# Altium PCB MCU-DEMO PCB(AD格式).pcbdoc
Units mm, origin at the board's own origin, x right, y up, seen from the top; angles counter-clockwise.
Board outline 119.08 x 143.32 mm, 2 copper layers (Top Layer, Bottom Layer); 31 components, 42 nets, 139 pads, 76 vias.
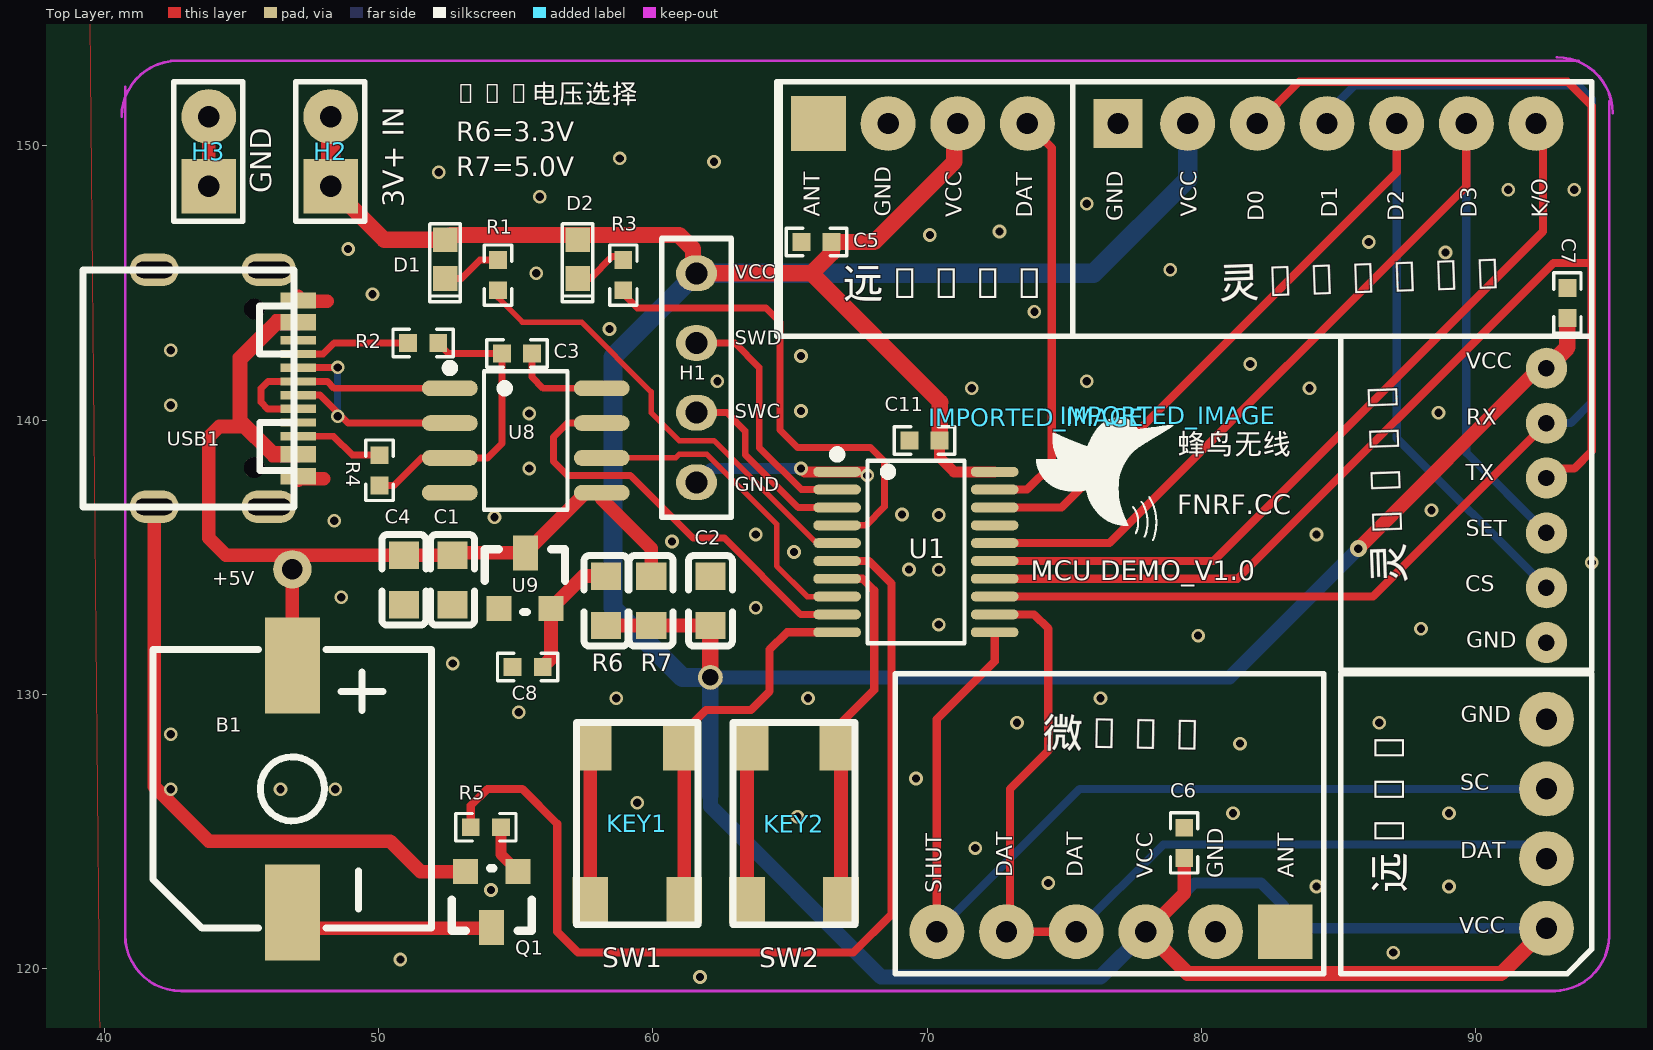
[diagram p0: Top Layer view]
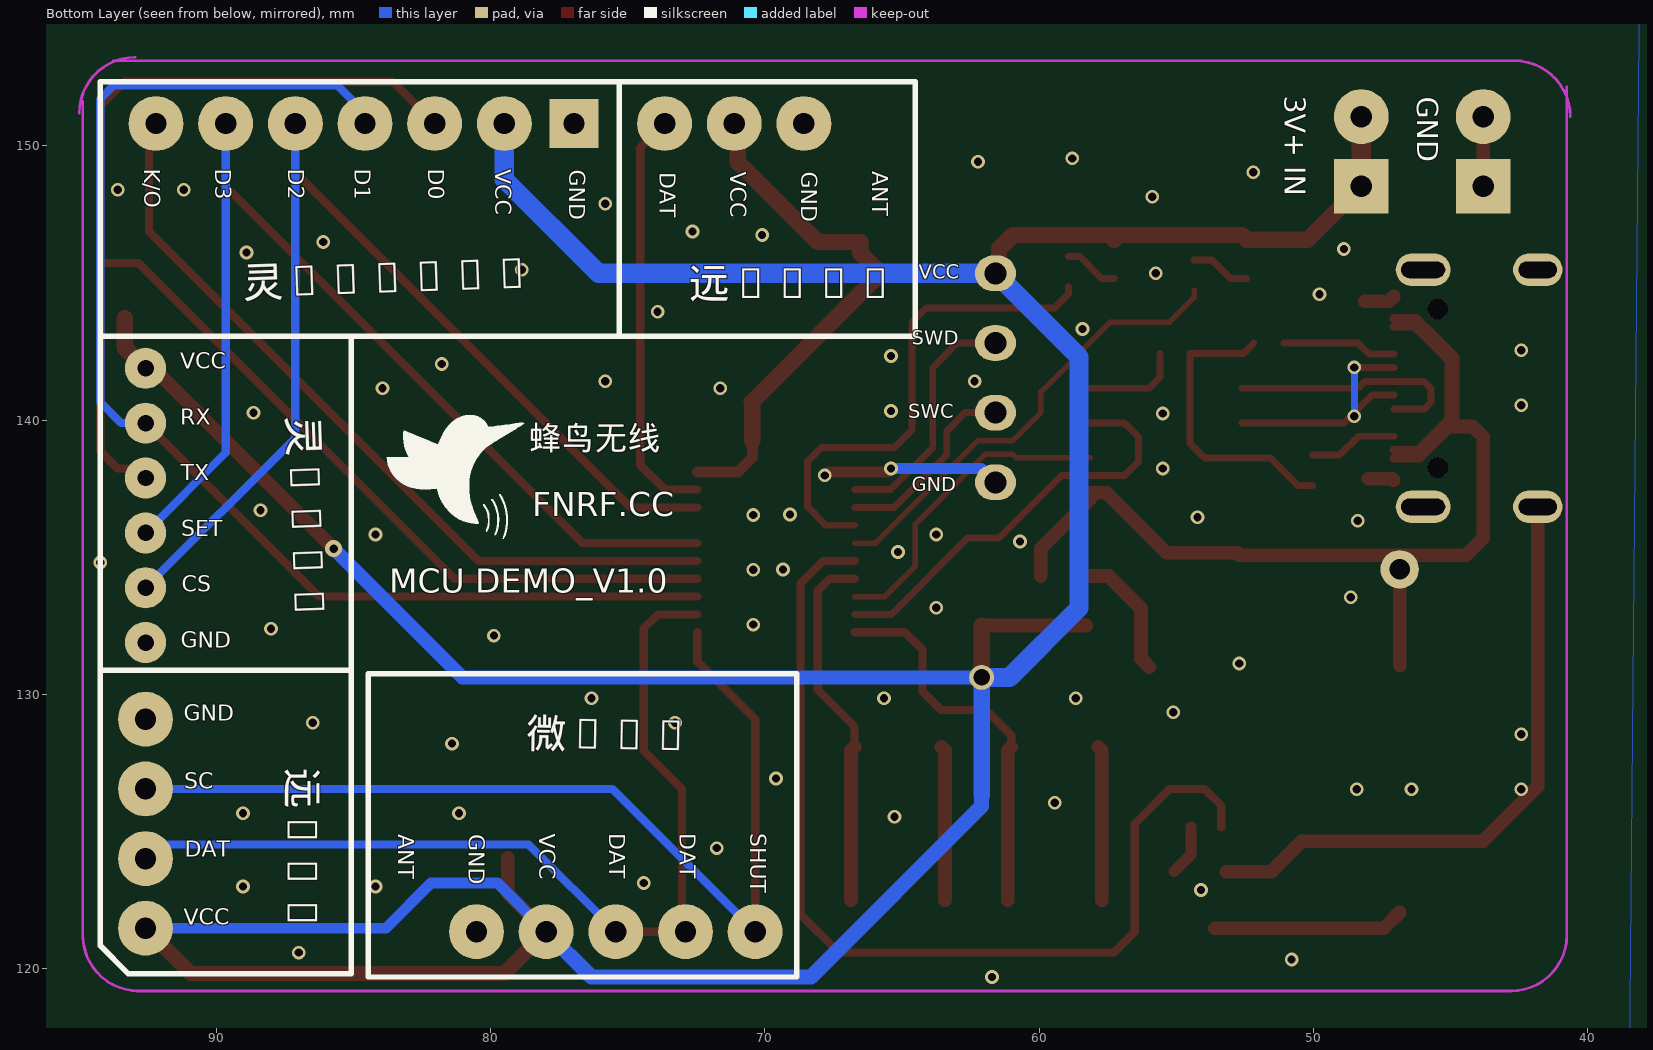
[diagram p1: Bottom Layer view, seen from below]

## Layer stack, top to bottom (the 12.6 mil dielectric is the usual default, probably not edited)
Top Layer: signal copper (thickness not stored)
Dielectric: dielectric 0.32, FR-4, Dk 4.8
Bottom Layer: signal copper (thickness not stored)

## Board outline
144.479,25.4 25.4,25.4 25.4,168.725 144.479,168.725

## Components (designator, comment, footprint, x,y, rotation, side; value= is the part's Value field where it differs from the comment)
B1 "有源蜂鸣器" BUZ-SMD_L9.6-W9.6-LS10.0-R 46.863,126.561 r90 top
C1 "10UF" C0603 52.705,134.181 r270 top
C2 "10UF" C0603 62.103,133.419 r270 top
C3 "0.1u-NC" R0603/0402 55.753,142.436 r180 top
C4 "0.1u-NC" C0603 50.927,134.181 r90 top
C5 "104" R0603/0402 66.675,146.5 r180 top
C6 "104" R0603/0402 79.375,123.894 r90 top
C7 "104" R0603/0402 93.345,144.976 r270 top
C8 "104" R0603/0402 54.737,131.006 r0 top
C11 "104" R0603/0402 70.612,139.261 r180 top
D1 "翠绿LED" LED0603 52.451,145.865 r270 top
D2 "翠绿LED" LED0603 57.277,145.865 r270 top
H1 "HDR-F-2.54_1x4" HDR-F-2.54_1X4 61.595,141.547 r90 top
H2 "3V+ IN" HDR-F-2.54_1X2 48.26,149.802 r90 top
H3 "GND" HDR-F-2.54_1X2 43.815,149.802 r90 top
IMPORTED_IMAGE "IMPORTED_IMAGE" IMPORTED_IMAGE 78.785,140.181 r0 top
IMPORTED_IMAGE "IMPORTED_IMAGE" IMPORTED_IMAGE 73.979,140.103 r0 top
KEY1 "SW1" KEY-SMD-4X4 59.436,125.291 r270 top
KEY2 "SW2" KEY-SMD-4X4 65.151,125.291 r270 top
Q1 "9014" SOT23 54.229,122.624 r90 top
R1 "1k" R0603/0402 54.356,145.992 r270 top
R2 "5.1k" R0603/0402 50.927,142.817 r0 top
R3 "1k" R0603/0402 58.928,145.992 r270 top
R4 "5.1k" R0603/0402 50.038,138.88 r270 top
R5 "1k" R0603/0402 53.213,125.164 r0 top
R6 "10UF" C0603 58.293,133.419 r270 top
R7 "10UF" C0603 59.944,133.419 r270 top
U1 "PY32F002AF15P6TU" TSSOP-20_L6.5-W4.4-P0.65-LS6.4-BL 69.596,135.197 r270 top
U8 "CH340N-NC" SOP-8_L5.0-W4.0-P1.27-LS6.0-BL 55.372,139.261 r270 top
U9 "XC6206P332" SOT23 55.245,134.054 r270 top
USB1 "USB3-TypeC-16p-2" USB-TYPE-C_16PIN-MALE-TYPE-C-31-M-12 44.45,141.166 r270 top

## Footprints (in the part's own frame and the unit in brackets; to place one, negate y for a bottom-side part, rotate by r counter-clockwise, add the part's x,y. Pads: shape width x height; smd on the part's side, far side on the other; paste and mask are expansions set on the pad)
BUZ-SMD_L9.6-W9.6-LS10.0-R [mm]
  rect 3.5x2 smd paste+0 mask+0.051: 1(4.5,0) 2(-4.5,0)
  silkscreen extent -5.08,-5.08 5.08,5.08
C0603 [mm]
  rect 1x1.1 smd paste+0 mask+0.102: 1(-0.9,0) 2(0.9,0)
  silkscreen extent -1.65,-0.8 1.65,0.8
HDR-F-2.54_1X2 [mm]
  rect 2x2 hole 0.78 paste+0 mask+0.102: 1(-1.27,0)
  round 2 hole 0.78 paste+0 mask+0.102: 2(1.27,0)
  silkscreen extent -2.54,-1.24 2.54,1.27
HDR-F-2.54_1X4 [mm]
  oval 1.3x1.5 hole 0.8 paste+0 mask+0.051: 1(-3.81,0) 2(-1.27,0) 3(1.27,0) 4(3.81,0)
  silkscreen extent -5.08,-1.27 5.08,1.27
IMPORTED_IMAGE [mm]
KEY-SMD-4X4 [mm]
  rect 1.7x1.3 smd paste+0 mask+0.102: 1(-2.794,1.587) 2(-2.794,-1.588) 3(2.794,1.715) 4(2.794,-1.714)
  silkscreen extent -3.68,-2.22 3.68,2.22
LED0603 [mm]
  rect 0.9x0.9 smd paste+0 mask+0.051: 1(-0.714,-0.012) 2(0.696,-0.012)
  silkscreen extent -1.3,-0.58 1.55,0.54
R0603/0402 [mm]
  rect 0.65x0.65 smd paste+0 mask+0.051: 1(0.152,0) 2(1.252,0)
  silkscreen extent -0.4,-0.5 1.8,0.5
SOP-8_L5.0-W4.0-P1.27-LS6.0-BL [mm]
  oval 0.574x2.036 smd paste+0 mask+0.051: 1(-1.905,-2.768) 2(-0.635,-2.768) 3(0.635,-2.768) 4(1.905,-2.768) 5(1.905,2.768) 6(0.635,2.768) 7(-0.635,2.768) 8(-1.905,2.768)
  silkscreen extent -2.79,-2.92 2.53,1.52
SOT23 [mil]
  rect 36x36 smd paste+0 mask+2: 1(36.19,41.31) 2(36.19,-33.68)
  rect 50x36 smd paste+0 mask+2: 3(-43.81,4.31)
  silkscreen extent -49,-54 41,61
TSSOP-20_L6.5-W4.4-P0.65-LS6.4-BL [mm]
  oval 0.364x1.742 smd paste+0 mask+0.051: 1(-2.925,-2.871) 2(-2.275,-2.871) 3(-1.625,-2.871) 4(-0.975,-2.871) 5(-0.325,-2.871) 6(0.325,-2.871) 7(0.975,-2.871) 8(1.625,-2.871) 9(2.275,-2.871) 10(2.925,-2.871) 11(2.925,2.871) 12(2.275,2.871) 13(1.625,2.871) 14(0.975,2.871) 15(0.325,2.871) 16(-0.325,2.871) 17(-0.975,2.871) 18(-1.625,2.871) 19(-2.275,2.871) 20(-2.925,2.871)
  silkscreen extent -3.71,-3.02 3.33,1.77
USB-TYPE-C_16PIN-MALE-TYPE-C-31-M-12 [mm]
  oval 1.2x2 hole 0.6 slot 1.6 at 90 deg paste+0 mask+0.051: 0(-4.32,1.556) 0(4.32,1.556)
  oval 1.2x1.8 hole 0.6 slot 1.4 at 90 deg paste+0 mask+0.051: 0(-4.32,-2.624) 0(4.32,-2.624)
  rect 0.3x1.3 smd paste+0 mask+0.051: A1(-3.35,2.623) A4(-2.55,2.623) A5(-1.25,2.623) A6(-0.25,2.623) A7(0.25,2.623) A8(1.25,2.624) A9(2.55,2.623) A12(3.35,2.623) B1(3.05,2.623) B4(2.25,2.623) B5(1.75,2.623) B6(0.75,2.623) B7(-0.75,2.623) B8(-1.75,2.624) B9(-2.25,2.623) B12(-3.05,2.623)
  round 0.75 hole 0.75 slot 0.755 at 0 deg unplated paste+0 mask+0.051: ""(-2.89,1.026) ""(2.89,1.026)
  silkscreen extent -4.32,-5.23 4.32,2.47

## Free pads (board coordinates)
  rect 2x2 smd paste+0 mask+0.102: 1(66.04,150.818) 1(83.058,121.354)
  rect 1.8x1.8 hole 0.78 paste+0 mask+0.102: 1(76.962,150.818)
  round 1.5 hole 0.6 paste+0 mask+0.102: 1(92.583,141.895) 2(92.583,139.895) 3(92.583,137.895) 4(92.583,135.895) 5(92.583,133.895) 6(92.583,131.895)
  round 2 hole 0.78 paste+0 mask+0.102: 2(68.58,150.818) 2(79.502,150.818) 2(80.518,121.354) 3(71.12,150.818) 3(77.978,121.354) 3(82.042,150.818) 3(92.583,121.481) 4(73.66,150.818) 4(75.438,121.354) 4(84.582,150.818) 4(92.583,124.021) 5(72.898,121.354) 5(87.122,150.818) 5(92.583,126.561) 6(70.358,121.354) 6(89.662,150.818) 6(92.583,129.101) 7(92.202,150.818)
  round 0.9 hole 0.6 paste+0 mask+0.102: 3(62.103,130.625)
  round 1.4 hole 0.75 paste+0 mask+0.102: 21(46.863,134.566)

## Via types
v1: diameter 0.5, hole 0.3, Top Layer to Bottom Layer, tented both sides, 75 vias
v2: diameter 0.62, hole 0.31, Top Layer to Bottom Layer, tented both sides, 1 vias

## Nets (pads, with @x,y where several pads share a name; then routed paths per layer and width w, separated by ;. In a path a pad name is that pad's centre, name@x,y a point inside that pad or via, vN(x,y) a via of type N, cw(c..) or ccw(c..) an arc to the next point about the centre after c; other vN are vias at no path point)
+5V: B1.1 C1.1 C4.2 pad.21 R7.1 U8.5 U9.3 USB1.A4 USB1.A9 USB1.B4 USB1.B9 | length 45.6
  Top Layer w0.3: 45.671,142.995 45.593,143.071 46.238,143.716 USB1.A4 ; 45.847,143.325 44.831,142.314 44.831,139.896 46.111,138.616 USB1.A9 ; USB1.B4 46.192,138.916 45.085,140.023 45.085,142.182 46.319,143.416 USB1.B9
  Top Layer w0.5: 45.012,139.769 44.196,139.769 43.815,139.388 43.815,135.705 44.439,135.081 48.529,135.081 ; B1.1 pad.21 46.863,135.08 50.927,135.08 C1.1 ; C1.1 52.791,135.167 U9.3 57.544,137.356 U8.5 58.14,137.128 59.944,135.324 R7.1
D1_2: D1.2 R1.1 | length 2.2
  Top Layer w0.25: D1.2 53.025,145.169 53.695,145.84 R1.1
D+: U8.1 USB1.A6 USB1.B6 | length 9.1
  Top Layer w0.25: USB1.B6 45.962,140.416 45.72,140.658 45.72,141.166 45.97,141.416 USB1.A6 ; USB1.A6@47.074,141.415 48.138,141.415 48.387,141.166 U8.1
D-: U8.2 USB1.A7 USB1.B7 | length 9.2
  Top Layer w0.25: USB1.A7 47.875,140.916 48.895,139.896 U8.2 ; USB1.B7 47.085,141.928 v1(48.514,141.928)
  Bottom Layer w0.25: v1(48.514,140.15) v1(48.514,141.928)
GND: C1.2 C2.1 C3.2 C4.1 C5.2 C6.2 C7.1 C8.1 C11.2 H1.1 H3.1 H3.2 KEY1.2 KEY1.4 KEY2.2 KEY2.4 pad.1@76.962,150.818 pad.2@68.58,150.818 pad.2@80.518,121.354 pad.6@92.583,129.101 pad.6@92.583,131.895 Q1.1 R2.2 R4.2 U1.1 U8.3 U9.2 USB1.0 USB1.A1 USB1.A12 USB1.B1 USB1.B12 | length 56.1
  Top Layer w0.25: R4.2 50.563,137.628 51.562,138.626 U8.3 53.975,138.626 54.5,139.152 C3.2 52.56,142.436 R2.2
  Top Layer w0.4: v1(65.405,138.245) 65.528,138.122 U1.1 67.687,138.122 v1(67.818,137.991)
  Top Layer w0.5: USB1.0@41.825,136.846 41.825,126.645 43.815,124.656 50.419,124.656 51.532,123.543 Q1.1 ; H3.1 H3.2 ; USB1.A12 47.121,137.864 48.006,137.864 ; USB1.A1 47.248,144.341 48.133,144.341 ; KEY1.4 57.721,127.958 KEY1.2 ; KEY2.4 63.436,127.958 KEY2.2
  Bottom Layer w0.4: H1.1 62.103,138.245 v1(65.405,138.245)
  other v1: 61.722,119.703 50.8,120.338 86.995,120.592 54.102,122.878 84.201,123.005 89.027,123.005 74.422,123.132 71.755,124.402 65.278,125.545 81.153,125.672 89.027,125.672 59.436,126.053 42.429,126.55 46.429,126.55 48.429,126.55 69.596,126.942 81.407,128.212 42.429,128.55 73.279,128.974 86.487,128.974 55.118,129.355 58.674,129.863 65.659,129.863 76.327,129.863 52.705,131.133 79.883,132.149 88.011,132.403 70.429,132.55 63.754,133.165 48.641,133.546 70.429,134.55 69.342,134.562 94.234,134.816 65.151,135.197 60.706,135.578 63.754,135.832 84.201,135.832 48.387,136.34 54.229,136.467 69.088,136.562 70.429,136.55 88.392,136.721 55.499,138.245 55.499,140.245 88.646,140.277 65.405,140.341 42.429,140.55 71.628,141.166 83.947,141.166 62.357,141.42 75.819,141.42 81.788,142.055 65.405,142.341 42.429,142.55 58.42,143.325 73.914,143.96 49.784,144.595 55.753,145.357 78.867,145.484 88.9,146.119 48.895,146.246 86.106,146.5 70.104,146.754 72.644,146.881 75.819,147.897 55.88,148.151 91.186,148.405 93.599,148.405 52.197,149.04 62.23,149.421 58.801,149.548
KEY_LED: pad.7 U1.15 | length 29
  Top Layer w0.3: U1.15 80.447,134.872 92.456,146.881 92.456,150.564 pad.7
M3_CS: pad.5@87.122,150.818 pad.5@92.583,133.895 U1.18 | length 40.7
  Top Layer w0.3: U1.18 74.904,136.822 87.122,149.04 pad.5@87.122,150.818
  Bottom Layer w0.3: pad.5@87.122,150.818 87.122,139.356 pad.5@92.583,133.895
M3_RXD: pad.2@92.583,139.895 pad.4@84.582,150.818 U1.13 | length 46.4
  Top Layer w0.3: U1.13 86.26,133.572 pad.2@92.583,139.895
  Bottom Layer w0.3: pad.4@84.582,150.818 84.582,151.199 85.598,152.215 93.726,152.215 94.234,151.707 94.234,140.658 93.472,139.896 pad.2@92.583,139.896
M3_SET: pad.4@92.583,135.895 pad.6@89.662,150.818 U1.16 | length 41
  Top Layer w0.3: U1.16 76.652,135.522 89.662,148.532 pad.6@89.662,150.818
  Bottom Layer w0.3: pad.6@89.662,150.818 89.662,138.816 pad.4@92.583,135.895
M3_TXD: pad.3@82.042,150.818 pad.3@92.583,137.895 U1.14 | length 54.7
  Top Layer w0.3: U1.14 81.32,134.222 92.837,145.738 94.234,145.738 94.234,145.405 ; pad.3@82.042,150.818 83.566,152.342 93.345,152.342 94.234,151.453 94.234,138.88 93.599,138.245 92.933,138.245 pad.3@92.583,137.895
MCU_BUZ: R5.1 U1.6 | length 36.1
  Top Layer w0.3: R5.1 53.365,125.951 53.975,126.561 55.245,126.561 56.515,125.291 56.515,121.354 57.277,120.592 67.31,120.592 68.707,121.989 68.707,134.054 67.889,134.872 U1.6
MCU_K1: KEY1.1 KEY1.3 U1.10 | length 14.2
  Top Layer w0.3: KEY1.1 61.023,128.519 61.94,129.436 63.581,129.436 64.262,130.117 64.262,131.641 64.894,132.271 U1.10@66.726,132.271
  Top Layer w0.5: KEY1.1 61.15,127.958 KEY1.3
MCU_K2: KEY2.1 KEY2.3 U1.7 | length 13.4
  Top Layer w0.3: U1.7 67.65,134.222 68.072,133.8 68.072,130.163 66.738,128.83 KEY2.1
  Top Layer w0.5: KEY2.1 66.865,127.958 KEY2.3
MCU_LED_G: R3.2 U1.4 | length 18.3
  Top Layer w0.25: R3.2@58.928,144.867 58.928,144.595 59.436,144.087 64.135,144.087 64.643,143.579 64.643,139.642 65.278,139.007 67.945,139.007 68.453,138.499 68.453,136.848 67.777,136.172 U1.4
MCU_LED_R: R1.2 U1.5 | length 16.8
  Top Layer w0.2: R1.2 54.356,144.468 55.245,143.579 57.404,143.579 59.944,141.039 59.944,140.277 60.96,139.261 62.23,139.261 65.969,135.522 U1.5
MCU_RF_OUT: pad.4@73.66,150.818 U1.19 | length 15.3
  Top Layer w0.3: U1.19 73.649,137.472 74.549,138.372 74.549,149.929 pad.4@73.66,150.818
PC_RX: U1.9 U8.7 | length 15.5
  Top Layer w0.25: U8.7 56.896,139.896 56.388,139.388 56.388,138.499 56.896,137.991 59.182,137.991 61.468,135.705 62.611,135.705 65.395,132.921 U1.9
PC_TX: U1.8 U8.6 | length 11.7
  Top Layer w0.2: U8.6 60.833,138.626 60.96,138.753 61.976,138.753 64.516,136.213 64.516,134.689 65.633,133.571 U1.8
Q1_3: B1.2 Q1.3 | length 7
  Top Layer w0.5: B1.2 47.443,121.481 53.594,121.481
R3_1: D2.2 R3.1 | length 2
  Top Layer w0.25: D2.2 57.724,145.169 58.521,145.967 R3.1@58.928,145.967
R5_2: Q1.2 R5.2 | length 1.9
  Top Layer w0.4: R5.2 54.465,124.162 Q1.2
RF_SHUT: pad.5@92.583,126.561 pad.6@70.358,121.354 U1.11 | length 36.6
  Top Layer w0.3: pad.6@70.358,121.354 70.358,129.101 72.467,131.21 U1.11
  Bottom Layer w0.3: pad.6@70.358,121.354 75.565,126.561 pad.5@92.964,126.561
RFDAT1: pad.4@75.438,121.354 pad.4@92.583,124.021 pad.5@72.898,121.354 U1.12 | length 35.7
  Top Layer w0.3: U1.12 73.903,132.922 74.422,132.403 74.422,127.958 73.025,126.561 73.025,121.481 72.898,121.354 pad.4@75.438,121.354
  Bottom Layer w0.3: pad.4@75.438,121.354 78.613,124.529 92.964,124.529 pad.4@92.964,124.021
S$7201: 
S$7211: 
S$7222: 
S$7295: 
S$7299: 
S$16717: 
S$16721: 
S$16725: 
SWC: H1.2 U1.3 | length 7.1
  Top Layer w0.25: H1.2 62.702,140.277 63.373,139.606 63.373,138.753 65.303,136.823 U1.3
SWD: H1.3 U1.2 | length 9.1
  Top Layer w0.25: H1.3 62.992,142.817 63.881,141.928 63.881,139.007 65.415,137.473 U1.2
U1_17: U1.17
U8_4: U8.4
USB1_A5: R2.1 USB1.A5 | length 4.2
  Top Layer w0.25: USB1.A5 47.986,142.416 48.387,142.817 R2.1
USB1_A8: USB1.A8
USB1_B5: R4.1 USB1.B5 | length 3.2
  Top Layer w0.25: USB1.B5 48.359,139.416 49.047,138.728 R4.1
USB1_B8: USB1.B8
V33: C8.2 R6.1 U9.1 | length 4.7
  Top Layer w0.5: C8.2 56.294,131.311 U9.1 57.478,134.319 R6.1
VCC: C2.2 C5.1 C6.1 C7.2 C11.1 D1.1 D2.1 H1.4 H2.1 H2.2 pad.1@92.583,141.895 pad.2@79.502,150.818 pad.3@62.103,130.625 pad.3@71.12,150.818 pad.3@77.978,121.354 pad.3@92.583,121.481 R6.2 R7.2 U1.20 | length 184.2
  Top Layer w0.4: C11.1 70.459,138.651 70.989,138.122 U1.20
  Top Layer w0.5: R6.2 R7.2 C2.2 ; pad.3@77.978,121.354 79.375,122.751 C6.1 ; v2(85.725,135.324) 92.296,141.895 pad.1@92.583,141.895
  Top Layer w0.55: pad.3@77.978,121.354 79.502,119.83 90.932,119.83 pad.3@92.583,121.481
  Top Layer w0.6: H2.1 50.213,146.579 D1.1 52.614,146.754 57.09,146.754 D2.1 ; 56.079,146.754 60.96,146.754 61.468,146.246 61.468,145.484 H1.4 65.786,145.357 ; pad.3@62.103,130.625 C2.2 ; C11.1 70.459,140.632 70.485,140.658 65.786,145.357 ; pad.3@71.12,150.818 70.993,150.691 70.993,149.421 68.072,146.5 C5.1 66.523,146.094 65.786,145.357 ; pad.1@92.583,141.895 93.345,142.657 C7.2
  Top Layer w0.7: H2.1 H2.2
  Bottom Layer w0.4: pad.3@77.978,121.354 79.756,123.132 82.169,123.132 83.82,121.481 pad.3@92.583,121.481
  Bottom Layer w0.5: pad.3@62.103,130.625 81.026,130.625 v2(85.725,135.324)
  Bottom Layer w0.55: 62.103,126.307 62.103,125.926 68.326,119.703 76.327,119.703 pad.3@77.978,121.354
  Bottom Layer w0.6: 62.103,126.307 pad.3@62.103,130.625
  Bottom Layer w0.7: pad.3@62.103,130.625 61.087,130.625 58.547,133.165 58.547,142.309 H1.4 76.073,145.357 79.502,148.786 pad.2@79.502,150.818
VV: C3.1 U8.8 | length 3.6
  Top Layer w0.25: C3.1 55.6,141.572 56.007,141.166 U8.8
pads on no net: USB1.

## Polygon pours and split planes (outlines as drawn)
GND on Bottom Layer (solid): 38.1,156.025 94.742,156.025 102.489,148.278 102.489,119.83 98.171,115.512 39.751,115.512 38.862,116.401 38.735,116.401 38.481,116.655
GND on Top Layer (solid): 39.497,154.628 96.139,154.628 103.886,146.881 103.886,118.433 99.568,114.115 41.148,114.115 40.259,115.004 40.132,115.004 39.878,115.258

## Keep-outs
Keep-Out Layer:
  lines w0.1 net S$7211: 40.64,151.072 cw(c42.672,151.072) 42.672,153.104 ; 40.767,121.227 ccw(c42.799,121.227) 42.799,119.195 ; 92.837,119.195 ccw(c92.837,121.227) 94.869,121.227 ; 92.964,153.231 cw(c92.964,151.199) 94.996,151.199

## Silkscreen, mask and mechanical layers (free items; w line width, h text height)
Top Overlay:
  lines w0.2 net S$16717: 85.09,119.83 85.09,130.752 94.234,130.752 94.234,120.719 93.345,119.83 85.09,119.83
  lines w0.2 net S$16721: 68.834,130.117 68.834,130.752 84.455,130.752 84.455,119.83 68.834,119.83 68.834,130.117 ; 68.834,130.117 68.834,130.117
  lines w0.2 net S$16725: 75.197,143.071 64.529,143.071 64.529,152.342 75.311,152.342 ; 75.425,152.342 64.643,152.342 64.643,143.071 75.311,143.071 ; 75.311,143.071 85.09,143.071 ; 75.311,143.071 75.311,152.342 ; 75.311,152.342 94.234,152.342 94.234,143.071 ; 85.09,143.071 94.234,143.071 ; 85.09,143.071 85.09,130.879 94.234,130.879 94.234,143.071
  text "VCC电压选择" at 52.705,151.326 h1.2
  text "R6=3.3V" at 52.832,149.929 h1.2
  text "R7=5.0V" at 52.832,148.659 h1.2
  text "ANT" at 66.294,147.419 h1 r90
  text "GND" at 68.876,147.414 h1 r90
  text "VCC" at 71.46,147.409 h1 r90
  text "VCC" at 80.034,147.424 h1 r90
  text "DAT" at 74.041,147.389 h1 r90
  text "D1" at 85.153,147.389 h1 r90
  text "D3" at 90.247,147.389 h1 r90
  text "K/O" at 92.837,147.389 h1 r90
  text "GND" at 77.343,147.259 h1 r90
  text "D0" at 82.469,147.262 h1 r90
  text "D2" at 87.573,147.262 h1 r90
  text "VCC" at 62.992,144.976 h0.9
  text "灵-Rx-M5" at 80.645,144.087 h1.9 r2
  text "远-T1L" at 66.929,144.079 h1.9
  text "SWD" at 62.992,142.563 h0.9
  text "VCC" at 89.667,141.674 h1
  text "SWC" at 62.992,139.896 h0.9
  text "RX" at 89.664,139.641 h1
  text "蜂鸟无线" at 79.121,138.499 h1.3
  text "TX" at 89.644,137.609 h1
  text "GND" at 62.992,137.229 h0.9
  text "FNRF.CC" at 79.121,136.34 h1.2
  text "SET" at 89.639,135.576 h1
  text "灵-TRx" at 87.757,134.054 h1.9 r92
  text "MCU DEMO_V1.0" at 73.787,133.927 h1.2
  text "+5V" at 43.942,133.8 h0.9
  text "CS" at 89.613,133.544 h1
  text "GND" at 89.662,131.514 h1
  text "GND" at 89.456,128.787 h1
  text "微-Rx" at 74.175,127.71 h1.9 r359
  text "SC" at 89.434,126.31 h1
  text "DAT" at 89.431,123.833 h1
  text "DAT" at 73.304,123.345 h1 r90
  text "DAT" at 75.87,123.345 h1 r90
  text "VCC" at 78.435,123.312 h1 r90
  text "GND" at 81,123.31 h1 r90
  text "ANT" at 83.566,123.32 h1 r90
  text "SHUT" at 70.739,122.751 h1 r90
  text "远-Rx" at 87.757,122.751 h1.9 r90
  text "VCC" at 89.408,121.1 h1
  text "GND" at 130.429,38.1 h0.9
Bottom Overlay:
  lines w0.2 net S$16717: 85.09,119.83 85.09,130.879 94.234,130.879 94.234,120.846 93.218,119.83 85.09,119.83
  lines w0.2 net S$16721: 68.834,130.117 68.834,130.752 84.455,130.752 84.455,119.703 68.834,119.703 68.834,130.117 ; 68.834,130.117 68.834,130.117
  lines w0.2 net S$16725: 75.448,152.342 64.516,152.342 64.516,143.071 75.311,143.071 ; 75.311,143.071 85.09,143.071 ; 75.311,143.071 75.311,152.342 94.234,152.342 94.234,143.071 ; 85.09,143.071 94.234,143.071 ; 85.09,143.071 85.09,130.879 94.234,130.879 94.234,143.071
  text "3V+ IN" at 51.308,151.834 h1.3 r90
  text "GND" at 46.482,151.785 h1.3 r90
  text "D0" at 82.469,149.164 h1 r90
  text "D1" at 85.153,149.164 h1 r90
  text "D2" at 87.573,149.164 h1 r90
  text "D3" at 90.247,149.164 h1 r90
  text "K/O" at 92.837,149.167 h1 r90
  text "GND" at 77.343,149.139 h1 r90
  text "VCC" at 80.034,149.144 h1 r90
  text "ANT" at 66.294,149.07 h1 r90
  text "GND" at 68.876,149.065 h1 r90
  text "VCC" at 71.46,149.06 h1 r90
  text "DAT" at 74.041,149.04 h1 r90
  text "VCC" at 64.389,144.976 h0.9
  text "远-T1L" at 72.771,144.087 h1.9
  text "灵-Rx-M5" at 89.027,144.094 h1.9 r358
  text "SWD" at 64.643,142.563 h0.9
  text "VCC" at 91.313,141.674 h1
  text "灵-TRx" at 87.749,140.15 h1.9 r88
  text "SWC" at 64.77,139.896 h0.9
  text "RX" at 91.31,139.641 h1
  text "蜂鸟无线" at 78.613,138.626 h1.5
  text "TX" at 91.29,137.609 h1
  text "GND" at 64.643,137.229 h0.9
  text "FNRF.CC" at 78.486,136.213 h1.5
  text "SET" at 91.285,135.576 h1
  text "CS" at 91.259,133.544 h1
  text "MCU DEMO_V1.0" at 83.693,133.419 h1.5
  text "GND" at 91.308,131.514 h1
  text "GND" at 91.186,128.847 h1
  text "微-Rx" at 78.74,127.704 h1.9 r1
  text "远-Rx" at 87.757,127.323 h1.9 r90
  text "SC" at 91.164,126.37 h1
  text "SHUT" at 70.739,124.938 h1 r90
  text "DAT" at 73.304,124.94 h1 r90
  text "DAT" at 75.87,124.94 h1 r90
  text "VCC" at 78.435,124.92 h1 r90
  text "GND" at 81,124.915 h1 r90
  text "ANT" at 83.566,124.91 h1 r90
  text "DAT" at 91.161,123.893 h1
  text "VCC" at 91.181,121.414 h1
